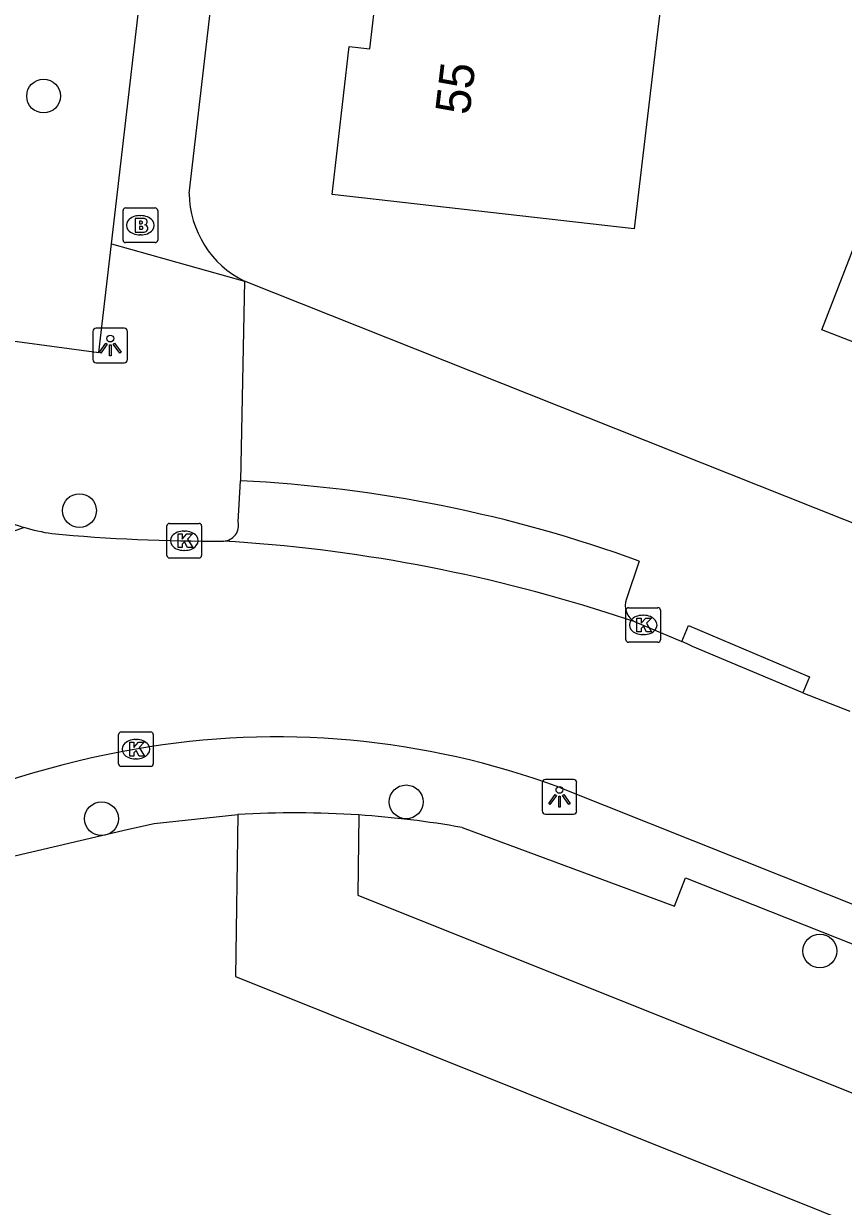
# Model space of a CAD drawing. Extents: x 161696 to 162377, y 380761 to 381673.
# Drawn here: x 161943.55 to 161967.25, y 380962.24 to 380996.44 of the extents above; entities that cross this region are included whole.
import ezdxf

# ---------------------------------------------------------------- set-up
doc = ezdxf.new("R2010")
doc.units = 0
for name, color, linetype in [('IMGEO_Boom', 7, 'Continuous'), ('IMGEO_Brandkraan', 7, 'Continuous'), ('IMGEO_Groenvoorziening', 7, 'Continuous'), ('IMGEO_Kolk', 7, 'Continuous'), ('IMGEO_Lichtpunt', 7, 'Continuous'), ('IMGEO_Pand', 7, 'Continuous'), ('IMGEO_Pand_nummerreeks', 7, 'Continuous'), ('IMGEO_Rijbaan_lokaal_open', 7, 'Continuous'), ('IMGEO_Voetpad_open', 7, 'Continuous')]:
    doc.layers.add(name, color=color, linetype=linetype)

msp = doc.modelspace()

# ---------------------------------------------------------------- linework, layer by layer
at = {"layer": 'IMGEO_Boom'}
for centre in [(161944.129, 380994.347), (161945.165, 380982.361), (161954.61, 380973.938), (161945.803, 380973.452), (161966.569, 380969.627)]:
    msp.add_circle(centre, 0.489, dxfattribs=at)
at = {"layer": 'IMGEO_Brandkraan'}
for p, q in [((161946.426, 380990.185), (161946.426, 380991.037)), ((161946.501, 380991.111), (161947.353, 380991.111)), ((161946.914, 380990.891), (161946.939, 380990.891)), ((161947.427, 380991.037), (161947.427, 380990.185)), ((161946.937, 380990.331), (161946.912, 380990.331)), ((161947.353, 380990.111), (161946.501, 380990.111))]:
    msp.add_line(p, q, dxfattribs=at)
for points in [[(161946.426, 380990.185), (161946.426, 380991.037)], [(161946.501, 380991.111), (161947.353, 380991.111)], [(161947.427, 380991.037), (161947.427, 380990.185)], [(161946.774, 380990.811), (161946.774, 380990.411), (161946.987, 380990.411)], [(161947.005, 380990.811), (161946.774, 380990.811)], [(161946.953, 380990.73), (161946.899, 380990.73), (161946.899, 380990.654)], [(161946.899, 380990.654), (161946.952, 380990.654)], [(161946.961, 380990.578), (161946.899, 380990.578), (161946.899, 380990.497)], [(161946.899, 380990.497), (161946.961, 380990.497)], [(161947.353, 380990.111), (161946.501, 380990.111)]]:
    msp.add_lwpolyline(points, dxfattribs=at)
for centre, radius, start, end in [((161946.503, 380991.035), 0.0765, 91.552, 178.448), ((161946.503, 380991.035), 0.0765, 91.552, 178.448), ((161947.351, 380991.035), 0.0765, 1.552, 88.448), ((161947.351, 380991.035), 0.0765, 1.552, 88.448), ((161946.954, 380990.692), 0.0379, 267.8285, 90.9355), ((161946.962, 380990.537), 0.0404, 269.8759, 90.5077), ((161947.009, 380990.666), 0.145, 59.4692, 91.5367), ((161947.034, 380990.713), 0.0922, 285.5137, 58.1501), ((161947.039, 380990.521), 0.105, 301.3115, 78.989), ((161946.503, 380990.187), 0.0765, 181.552, 268.448), ((161946.503, 380990.187), 0.0765, 181.552, 268.448), ((161946.993, 380990.662), 0.251, 268.6676, 293.5347), ((161947.351, 380990.187), 0.0765, 271.552, 358.448), ((161947.351, 380990.187), 0.0765, 271.552, 358.448)]:
    msp.add_arc(centre, radius, start, end, dxfattribs=at)
for centre, major_axis, ratio, start_param, end_param in [((161946.913, 380990.611), (-0.387, 0.002), 0.722429, 4.712389, 7.853982), ((161946.938, 380990.611), (-0.39, 0.002), 0.717154, 1.570796, 4.712389)]:
    msp.add_ellipse(centre, major_axis=major_axis, ratio=ratio, start_param=start_param, end_param=end_param, dxfattribs=at)
at = {"layer": 'IMGEO_Groenvoorziening'}
for points in [[(161949.741, 380973.571), (161949.675, 380968.888), (161952.35, 380967.817), (161972.334, 380959.806), (161976.13, 380958.282), (161998.268, 380949.439), (161996.826, 380953.786)], [(161953.242, 380973.561), (161953.209, 380971.244), (161996.826, 380953.786)]]:
    msp.add_lwpolyline(points, dxfattribs=at)
at = {"layer": 'IMGEO_Kolk'}
for p, q in [((161947.77, 380981.99), (161948.622, 380981.99)), ((161947.695, 380981.064), (161947.695, 380981.916)), ((161948.183, 380981.77), (161948.208, 380981.77)), ((161948.696, 380981.916), (161948.696, 380981.064)), ((161948.622, 380980.99), (161947.77, 380980.99)), ((161948.206, 380981.21), (161948.181, 380981.21)), ((161961.037, 380979.554), (161961.889, 380979.554)), ((161960.962, 380978.628), (161960.962, 380979.48)), ((161961.45, 380979.334), (161961.475, 380979.334)), ((161961.963, 380979.48), (161961.963, 380978.628)), ((161961.889, 380978.554), (161961.037, 380978.554)), ((161961.473, 380978.774), (161961.448, 380978.774)), ((161946.298, 380975.035), (161946.298, 380975.887)), ((161946.373, 380975.961), (161947.225, 380975.961)), ((161947.299, 380975.887), (161947.299, 380975.035)), ((161946.786, 380975.741), (161946.811, 380975.741)), ((161946.809, 380975.181), (161946.784, 380975.181)), ((161947.225, 380974.961), (161946.373, 380974.961))]:
    msp.add_line(p, q, dxfattribs=at)
for points in [[(161947.77, 380981.99), (161948.622, 380981.99)], [(161947.695, 380981.064), (161947.695, 380981.916)], [(161948.016, 380981.69), (161948.139, 380981.69), (161948.139, 380981.539), (161948.269, 380981.69), (161948.433, 380981.69), (161948.287, 380981.539), (161948.44, 380981.29), (161948.288, 380981.29), (161948.203, 380981.454), (161948.139, 380981.387), (161948.139, 380981.29), (161948.016, 380981.29), (161948.016, 380981.69)], [(161948.696, 380981.916), (161948.696, 380981.064)], [(161948.622, 380980.99), (161947.77, 380980.99)], [(161961.037, 380979.554), (161961.889, 380979.554)], [(161960.962, 380978.628), (161960.962, 380979.48)], [(161961.283, 380979.254), (161961.406, 380979.254), (161961.406, 380979.103), (161961.536, 380979.254), (161961.7, 380979.254), (161961.554, 380979.103), (161961.707, 380978.854), (161961.555, 380978.854), (161961.47, 380979.018), (161961.406, 380978.951), (161961.406, 380978.854), (161961.283, 380978.854), (161961.283, 380979.254)], [(161961.963, 380979.48), (161961.963, 380978.628)], [(161961.889, 380978.554), (161961.037, 380978.554)], [(161946.298, 380975.035), (161946.298, 380975.887)], [(161946.373, 380975.961), (161947.225, 380975.961)], [(161947.299, 380975.887), (161947.299, 380975.035)], [(161946.619, 380975.661), (161946.742, 380975.661), (161946.742, 380975.51), (161946.872, 380975.661), (161947.036, 380975.661), (161946.89, 380975.51), (161947.043, 380975.261), (161946.891, 380975.261), (161946.806, 380975.425), (161946.742, 380975.358), (161946.742, 380975.261), (161946.619, 380975.261), (161946.619, 380975.661)], [(161947.225, 380974.961), (161946.373, 380974.961)]]:
    msp.add_lwpolyline(points, dxfattribs=at)
for centre, start, end in [((161947.772, 380981.914), 91.552, 178.448), ((161947.772, 380981.914), 91.552, 178.448), ((161948.62, 380981.914), 1.552, 88.448), ((161948.62, 380981.914), 1.552, 88.448), ((161947.772, 380981.066), 181.552, 268.448), ((161947.772, 380981.066), 181.552, 268.448), ((161948.62, 380981.066), 271.552, 358.448), ((161948.62, 380981.066), 271.552, 358.448), ((161961.039, 380979.478), 91.552, 178.448), ((161961.039, 380979.478), 91.552, 178.448), ((161961.887, 380979.478), 1.552, 88.448), ((161961.887, 380979.478), 1.552, 88.448), ((161961.039, 380978.63), 181.552, 268.448), ((161961.039, 380978.63), 181.552, 268.448), ((161961.887, 380978.63), 271.552, 358.448), ((161961.887, 380978.63), 271.552, 358.448), ((161946.375, 380975.885), 91.552, 178.448), ((161946.375, 380975.885), 91.552, 178.448), ((161947.223, 380975.885), 1.552, 88.448), ((161947.223, 380975.885), 1.552, 88.448), ((161946.375, 380975.037), 181.552, 268.448), ((161946.375, 380975.037), 181.552, 268.448), ((161947.223, 380975.037), 271.552, 358.448), ((161947.223, 380975.037), 271.552, 358.448)]:
    msp.add_arc(centre, 0.0765, start, end, dxfattribs=at)
for centre, major_axis, ratio, start_param, end_param in [((161948.182, 380981.49), (-0.387, 0.002), 0.722429, 4.712389, 7.853982), ((161948.207, 380981.49), (-0.39, 0.002), 0.717154, 1.570796, 4.712389), ((161961.449, 380979.054), (-0.387, 0.002), 0.722429, 4.712389, 7.853982), ((161961.474, 380979.054), (-0.39, 0.002), 0.717154, 1.570796, 4.712389), ((161946.785, 380975.461), (-0.387, 0.002), 0.722429, 4.712389, 7.853982), ((161946.81, 380975.461), (-0.39, 0.002), 0.717154, 1.570796, 4.712389)]:
    msp.add_ellipse(centre, major_axis=major_axis, ratio=ratio, start_param=start_param, end_param=end_param, dxfattribs=at)
at = {"layer": 'IMGEO_Lichtpunt'}
for p, q in [((161945.557, 380987.539), (161945.557, 380986.732)), ((161945.557, 380987.539), (161945.557, 380986.732)), ((161946.459, 380987.634), (161945.651, 380987.634)), ((161946.459, 380987.634), (161945.651, 380987.634)), ((161946.553, 380986.732), (161946.553, 380987.539)), ((161946.553, 380986.732), (161946.553, 380987.539)), ((161945.651, 380986.638), (161946.459, 380986.638)), ((161945.651, 380986.638), (161946.459, 380986.638)), ((161958.543, 380974.489), (161958.543, 380973.682)), ((161958.543, 380974.489), (161958.543, 380973.682)), ((161959.445, 380974.584), (161958.637, 380974.584)), ((161959.445, 380974.584), (161958.637, 380974.584)), ((161959.539, 380973.682), (161959.539, 380974.489)), ((161959.539, 380973.682), (161959.539, 380974.489)), ((161958.637, 380973.588), (161959.445, 380973.588)), ((161958.637, 380973.588), (161959.445, 380973.588))]:
    msp.add_line(p, q, dxfattribs=at)
for points in [[(161945.931, 380987.203), (161945.97, 380987.175), (161945.782, 380986.913), (161945.744, 380986.94), (161945.931, 380987.203)], [(161946.033, 380987.155), (161946.08, 380987.155), (161946.08, 380986.833), (161946.033, 380986.833), (161946.033, 380987.155)], [(161946.143, 380987.175), (161946.181, 380987.202), (161946.368, 380986.94), (161946.329, 380986.912), (161946.143, 380987.175)], [(161958.917, 380974.153), (161958.956, 380974.125), (161958.768, 380973.863), (161958.73, 380973.89), (161958.917, 380974.153)], [(161959.019, 380974.105), (161959.066, 380974.105), (161959.066, 380973.783), (161959.019, 380973.783), (161959.019, 380974.105)], [(161959.129, 380974.125), (161959.167, 380974.152), (161959.354, 380973.89), (161959.315, 380973.862), (161959.129, 380974.125)]]:
    msp.add_lwpolyline(points, dxfattribs=at)
for centre in [(161946.056, 380987.337), (161959.042, 380974.287)]:
    msp.add_circle(centre, 0.0994, dxfattribs=at)
for centre, start, end in [((161945.651, 380987.539), 90, 180), ((161945.651, 380987.539), 90, 180), ((161946.459, 380987.539), 0, 90), ((161946.459, 380987.539), 0, 90), ((161945.651, 380986.732), 180, 270), ((161945.651, 380986.732), 180, 270), ((161946.459, 380986.732), 270, 0), ((161946.459, 380986.732), 270, 360), ((161958.637, 380974.489), 90, 180), ((161958.637, 380974.489), 90, 180), ((161959.445, 380974.489), 0, 90), ((161959.445, 380974.489), 0, 90), ((161958.637, 380973.682), 180, 270), ((161958.637, 380973.682), 180, 270), ((161959.445, 380973.682), 270, 0), ((161959.445, 380973.682), 270, 360)]:
    msp.add_arc(centre, 0.0946, start, end, dxfattribs=at)
at = {"layer": 'IMGEO_Pand'}
for points in [[(161961.979, 380997.069), (161961.838, 380995.884), (161961.198, 380990.504), (161952.471, 380991.505), (161952.962, 380995.777), (161953.559, 380995.709), (161953.826, 380998.04)], [(161973.383, 380995.711), (161969.761, 380986.373), (161966.628, 380987.588), (161968.991, 380993.681), (161969.291, 380996.198)]]:
    msp.add_lwpolyline(points, dxfattribs=at)
at = {"layer": 'IMGEO_Rijbaan_lokaal_open'}
for points in [[(161930.016, 380974.84), (161934.38, 380977.774), (161938.805, 380980.142), (161943.553, 380981.877)], [(161961.226, 380979.141), (161960.392, 380979.413)], [(161961.226, 380979.141), (161962.58, 380978.579)], [(161966.073, 380977.095), (161962.887, 380978.43), (161962.734, 380978.506), (161962.58, 380978.579)], [(161966.073, 380977.095), (161967.438, 380976.557)], [(161959.048, 380974.354), (161995.08, 380959.99), (161997.359, 380959.087)]]:
    msp.add_lwpolyline(points, dxfattribs=at)
for centre, radius, start, end in [((161945.397, 380988.258), 6.642, 230.6485, 253.8843), ((161945.426, 380988.382), 6.769, 253.9323, 260.9952), ((161949.117, 381033.704), 52.225, 264.782, 270.2319), ((161946.593, 380936.194), 45.369, 72.2923, 86.5434), ((161950.876, 380952.275), 23.542, 69.6881, 99.9619), ((161951.263, 380949.474), 26.369, 99.7386, 130.1616)]:
    msp.add_arc(centre, radius, start, end, dxfattribs=at)
at = {"layer": 'IMGEO_Voetpad_open'}
for points in [[(161948.338, 380991.533), (161949.325, 381000), (161949.809, 381004.154), (161953.362, 381034.648)], [(161946.09, 380990.07), (161947.761, 381004.439), (161945.724, 381004.682), (161944.504, 381002.998), (161943.607, 381002.228), (161936.683, 380996.851)], [(161936.683, 380996.851), (161941.788, 380987.461), (161945.725, 380986.932), (161946.09, 380990.07)], [(161946.09, 380990.07), (161949.937, 380988.995)], [(161949.937, 380988.995), (161949.826, 380983.222)], [(161968.113, 380981.766), (161949.937, 380988.995)], [(161949.753, 380982.04), (161949.826, 380983.222)], [(161961.345, 380980.901), (161960.979, 380979.808)], [(161962.58, 380978.579), (161962.776, 380979.038), (161966.269, 380977.556), (161966.073, 380977.095)], [(161943.009, 380972.315), (161946.586, 380973.146), (161947.324, 380973.318), (161949.741, 380973.571)], [(161956.227, 380973.198), (161962.366, 380970.919), (161962.683, 380971.744), (161995.135, 380958.886)]]:
    msp.add_lwpolyline(points, dxfattribs=at)
for centre, radius, start, end in [((161951.196, 380991.561), 2.858, 180.5586, 243.8652), ((161947.938, 380944.105), 39.162, 69.9795, 87.2362), ((161949.311, 380981.934), 0.454, 272.0846, 13.5236), ((161961.475, 380979.612), 0.533, 158.4479, 242.1928), ((161951.412, 380945.737), 27.884, 86.237, 93.4356), ((161951.388, 380945.864), 27.759, 79.9616, 86.1713)]:
    msp.add_arc(centre, radius, start, end, dxfattribs=at)

# ---------------------------------------------------------------- texts
at = {"layer": 'IMGEO_Pand_nummerreeks'}
msp.add_text('55', height=1, rotation=83.2138, dxfattribs=at).set_placement((161956.439, 380993.778))

doc.saveas('drawing.dxf')
